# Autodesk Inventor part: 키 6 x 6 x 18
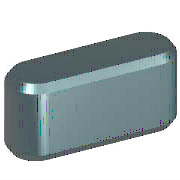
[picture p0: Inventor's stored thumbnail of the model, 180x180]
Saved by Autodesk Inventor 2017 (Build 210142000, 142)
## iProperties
IsCustomPart: 1
Created: 2012-02
Part Number: 키 6 x 6 x 18
Material: 강철, 연강
Description: 키 및 해당 키홈
Document SubType Name: Modeling
Standard: KS B 1311
Designer: mduedu
Standards Organization: KS
Language: ko-KR
Size Designation: 6 x 6 x 18
Categories: <MemberInstance><Categories><Category DisplayName="샤프트 부품" InternalName="7f7aeb1f-a693-4053-b835-cee3144e0d98" Mnemonic="SHFT"><Category DisplayName="키" Interna
Density: 1 g/cm^3
Appearance: 노란색
Author: mduedu
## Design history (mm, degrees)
workplane "Work Plane1"
workplane "Work Plane2"
sketch "스케치1"
  geometry: L1 (3, 3)-(15, 3); L2 (15, -3)-(3, -3); L3 (0, 9.4)-(0, -7.4) reference; L4 (-5, 0)-(30, 0) reference; L5 (18, 0)-(18, 7); A1 r 3 centre (3, 0) between (3, 3) and (3, -3); A2 r 3 centre (15, 0) between (15, -3) and (15, 3)
  constraints: 6 end point, 5 point on circle, 4 tangent, 3 point on line, 2 centre point, 1 horizontal, 1 parallel, 1 perpendicular
  dimensions: "d0" = 3 radius of A1 (= 0.5 x PB); "d13" = 3 radius of A2 (= 0.5 x PB); "d14" = 18 distance between parallel lines of L5 L3 (= NLG)
extrude "본체1" new body sketch "스케치1" taper "d3" = 0 deg; stored distance "d4" = 10
workplane "Work Plane3"
body "Solid1"
chamfer "모따기1" distance "d8" = 0.4 (= PHH); stored, may be unused: second distance "d9" = 0.4 (= PHH), angle "d15" = 45 deg
other parameters: "d1" = -3.5 (= -PNT), "d2" = 2.5 (= PH - PNT), "NLG" = 18 [user parameter; used in 3 equation terms], "PB" = 6 [user parameter; used in 2 equation terms], "PNT" = 3.5 [user parameter; used in 2 equation terms], "PH" = 6 [user parameter; used in 1 equation term], "PHH" = 0.4 [user parameter; used in 2 equation terms], "d10" = 0, "d16" = 0, "d17" = 0, "d18" = 0, "WDMIN" = 17 [user parameter], "PLB2" = 18 (= NLG) [user parameter], "WDMAX" = 22 [user parameter], "PLB1" = 18 (= NLG) [user parameter], "RR" = 0.16 [user parameter], "PUEB" = 2.8 [user parameter]
